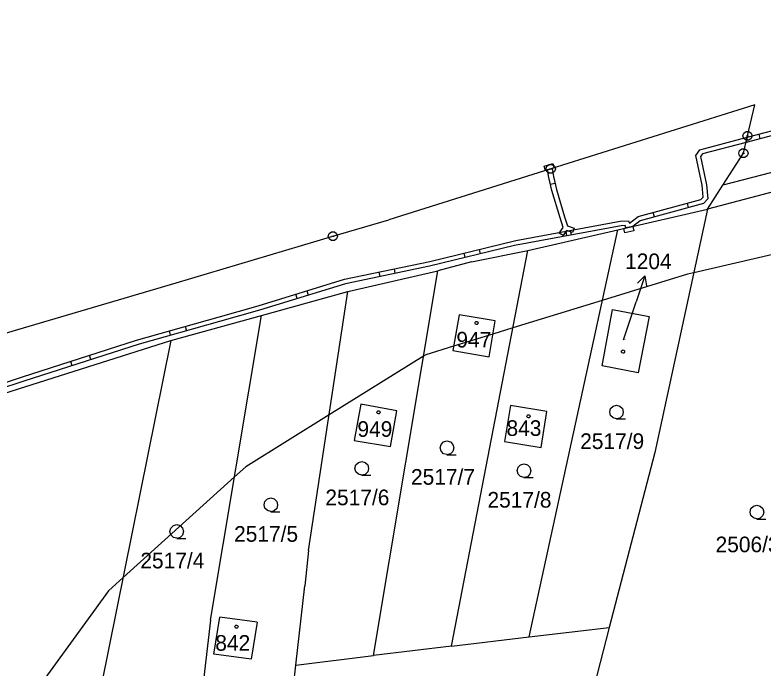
# Model space of a CAD drawing. Extents: x -760611 to -758411, y -1176479 to -1174807.
# Drawn here: x -759359.7 to -759278.5, y -1175126.3 to -1175055.4 of the extents above; entities that cross this region are included whole.
import ezdxf

# ---------------------------------------------------------------- set-up
doc = ezdxf.new("R2010")
doc.units = 0
for name, color, linetype in [('1', 7, 'Continuous'), ('11', 7, 'Continuous'), ('12', 7, 'Continuous'), ('13', 7, 'Continuous'), ('2', 7, 'Continuous'), ('3', 7, 'Continuous'), ('5', 7, 'Continuous'), ('7', 7, 'Continuous'), ('8', 7, 'Continuous')]:
    doc.layers.add(name, color=color, linetype=linetype)

msp = doc.modelspace()

# ---------------------------------------------------------------- linework, layer by layer
at = {"layer": '1'}
for p, q in [((-759279.37, -1175065.13), (-759301.53, -1175072.1)), ((-759280.16, -1175068.52), (-759279.37, -1175065.13)), ((-759258.67, -1175067.6), (-759282.82, -1175073.86)), ((-759280.6, -1175070.4), (-759280.16, -1175068.52)), ((-759261.9, -1175070.45), (-759284.49, -1175076.48)), ((-759282.82, -1175073.86), (-759280.6, -1175070.4)), ((-759301.53, -1175072.1), (-759319.13, -1175077.63)), ((-759284.49, -1175076.48), (-759282.82, -1175073.86)), ((-759294.26, -1175078.71), (-759284.49, -1175076.48)), ((-759284.49, -1175076.48), (-759290.24, -1175102.91)), ((-759325.19, -1175079.42), (-759319.13, -1175077.63)), ((-759342.24, -1175084.47), (-759325.19, -1175079.42)), ((-759304.03, -1175080.95), (-759294.26, -1175078.71)), ((-759303.86, -1175122.94), (-759294.26, -1175078.71)), ((-759312.31, -1175123.94), (-759304.03, -1175080.95)), ((-759310.13, -1175082.21), (-759304.03, -1175080.95)), ((-759310.13, -1175082.21), (-759313.8, -1175083.18)), ((-759323.57, -1175085.41), (-759313.8, -1175083.18)), ((-759320.78, -1175124.97), (-759313.8, -1175083.18)), ((-759367.91, -1175092.06), (-759342.24, -1175084.47)), ((-759332.94, -1175088.01), (-759323.57, -1175085.41)), ((-759327.86, -1175113.56), (-759323.57, -1175085.41)), ((-759295.95, -1175093.48), (-759294.82, -1175087.38)), ((-759294.82, -1175087.38), (-759290.84, -1175088.13)), ((-759342.79, -1175090.74), (-759332.94, -1175088.01)), ((-759338.48, -1175121.14), (-759332.94, -1175088.01)), ((-759311.49, -1175087.95), (-759312.16, -1175091.83)), ((-759307.58, -1175088.59), (-759311.49, -1175087.95)), ((-759290.84, -1175088.13), (-759292.04, -1175094.25)), ((-759308.22, -1175092.52), (-759307.58, -1175088.59)), ((-759367.67, -1175098.62), (-759342.79, -1175090.74)), ((-759342.79, -1175090.74), (-759352.98, -1175141.22)), ((-759312.16, -1175091.83), (-759308.22, -1175092.52)), ((-759292.04, -1175094.25), (-759295.95, -1175093.48)), ((-759322.17, -1175097.65), (-759322.9, -1175101.62)), ((-759318.26, -1175098.38), (-759322.17, -1175097.65)), ((-759305.9, -1175097.82), (-759306.54, -1175101.72)), ((-759301.95, -1175098.47), (-759305.9, -1175097.82)), ((-759318.94, -1175102.27), (-759318.26, -1175098.38)), ((-759302.59, -1175102.37), (-759301.95, -1175098.47)), ((-759322.9, -1175101.62), (-759318.94, -1175102.27)), ((-759306.54, -1175101.72), (-759302.59, -1175102.37)), ((-759290.24, -1175102.91), (-759295.17, -1175121.91)), ((-759327.86, -1175113.56), (-759328.24, -1175117.41)), ((-759329.21, -1175126), (-759328.24, -1175117.41)), ((-759338.12, -1175124.82), (-759337.47, -1175120.8)), ((-759333.44, -1175121.34), (-759337.47, -1175120.8)), ((-759338.48, -1175121.14), (-759340.03, -1175133.95)), ((-759333.44, -1175121.34), (-759334.07, -1175125.37)), ((-759303.86, -1175122.94), (-759295.17, -1175121.91)), ((-759295.17, -1175121.91), (-759298.25, -1175133.73)), ((-759312.31, -1175123.94), (-759303.86, -1175122.94)), ((-759312.31, -1175123.94), (-759320.78, -1175124.97)), ((-759334.07, -1175125.37), (-759338.12, -1175124.82)), ((-759329.21, -1175126), (-759320.78, -1175124.97)), ((-759330.67, -1175137.98), (-759329.21, -1175126))]:
    msp.add_line(p, q, dxfattribs=at)
at = {"layer": '11'}
msp.add_lwpolyline([(-759277.4, -1175081.41), (-759285.99, -1175083.38), (-759286.68, -1175083.54), (-759295.93, -1175086.38), (-759305.65, -1175089.38), (-759307.82, -1175090.04), (-759312.08, -1175091.35), (-759315.12, -1175092.29), (-759315.34, -1175092.43), (-759325.61, -1175098.82), (-759334.67, -1175104.46), (-759335.87, -1175105.55), (-759347.99, -1175116.51), (-759349.56, -1175117.93), (-759372.57, -1175149.55), (-759378.11, -1175156.29), (-759381.94, -1175161.35), (-759383.07, -1175162.46), (-759387.05, -1175166.4), (-759387.91, -1175169.78), (-759407.11, -1175194.59)], dxfattribs=at)
at = {"layer": '12'}
for p, q in [((-759295.95, -1175093.48), (-759294.82, -1175087.38)), ((-759294.82, -1175087.38), (-759290.84, -1175088.13)), ((-759311.49, -1175087.95), (-759312.16, -1175091.83)), ((-759307.58, -1175088.59), (-759311.49, -1175087.95)), ((-759290.84, -1175088.13), (-759292.04, -1175094.25)), ((-759308.22, -1175092.52), (-759307.58, -1175088.59)), ((-759312.16, -1175091.83), (-759308.22, -1175092.52)), ((-759292.04, -1175094.25), (-759295.95, -1175093.48)), ((-759322.17, -1175097.65), (-759322.9, -1175101.62)), ((-759318.26, -1175098.38), (-759322.17, -1175097.65)), ((-759305.9, -1175097.82), (-759306.54, -1175101.72)), ((-759301.95, -1175098.47), (-759305.9, -1175097.82)), ((-759318.94, -1175102.27), (-759318.26, -1175098.38)), ((-759302.59, -1175102.37), (-759301.95, -1175098.47)), ((-759322.9, -1175101.62), (-759318.94, -1175102.27)), ((-759306.54, -1175101.72), (-759302.59, -1175102.37)), ((-759338.12, -1175124.82), (-759337.47, -1175120.8)), ((-759333.44, -1175121.34), (-759337.47, -1175120.8)), ((-759333.44, -1175121.34), (-759334.07, -1175125.37)), ((-759334.07, -1175125.37), (-759338.12, -1175124.82))]:
    msp.add_line(p, q, dxfattribs=at)
at = {"layer": '13'}
for p, q in [((-759285.33, -1175070.01), (-759280.19, -1175068.65)), ((-759280.19, -1175068.65), (-759280.32, -1175069.22)), ((-759278.78, -1175068.818), (-759278.907, -1175068.335)), ((-759280.32, -1175069.22), (-759285.03, -1175070.45)), ((-759285.78, -1175070.64), (-759285.33, -1175070.01)), ((-759285.03, -1175070.45), (-759285.25, -1175070.75)), ((-759285.1, -1175073.88), (-759285.78, -1175070.64)), ((-759285.25, -1175070.75), (-759284.6, -1175073.82)), ((-759301.87, -1175072.2), (-759301.39, -1175072.05)), ((-759301.39, -1175072.05), (-759301.87, -1175072.2)), ((-759301.564, -1175073.756), (-759301.077, -1175073.64)), ((-759284.98, -1175075.17), (-759285.1, -1175073.88)), ((-759284.6, -1175073.82), (-759284.46, -1175075.35)), ((-759285.21, -1175075.42), (-759284.98, -1175075.17)), ((-759284.46, -1175075.35), (-759284.95, -1175075.86)), ((-759292.03, -1175077.27), (-759285.21, -1175075.42)), ((-759284.95, -1175075.86), (-759291.81, -1175077.73)), ((-759286.722, -1175075.83), (-759286.591, -1175076.313)), ((-759290.256, -1175077.306), (-759290.388, -1175076.824)), ((-759305.31, -1175079.88), (-759293.99, -1175077.77)), ((-759293.99, -1175077.77), (-759293.07, -1175077.74)), ((-759293.07, -1175077.74), (-759292.99, -1175077.98)), ((-759292.99, -1175077.98), (-759292.03, -1175077.27)), ((-759291.81, -1175077.73), (-759292.63, -1175078.34)), ((-759293.87, -1175078.27), (-759305.47, -1175080.42)), ((-759293.43, -1175078.26), (-759293.87, -1175078.27)), ((-759293.6, -1175078.56), (-759293.36, -1175078.5)), ((-759293.49, -1175079.05), (-759293.6, -1175078.56)), ((-759293.36, -1175078.5), (-759293.43, -1175078.26)), ((-759292.63, -1175078.34), (-759293.36, -1175078.5)), ((-759293.36, -1175078.5), (-759292.63, -1175078.34)), ((-759292.63, -1175078.34), (-759292.51, -1175078.82)), ((-759299.903, -1175078.872), (-759299.812, -1175079.364)), ((-759299.278, -1175079.272), (-759299.369, -1175078.781)), ((-759292.51, -1175078.82), (-759293.49, -1175079.05)), ((-759314.65, -1175082.15), (-759305.31, -1175079.88)), ((-759305.47, -1175080.42), (-759314.69, -1175082.67)), ((-759309.306, -1175080.851), (-759309.188, -1175081.337)), ((-759310.813, -1175081.724), (-759310.932, -1175081.238)), ((-759323.94, -1175084.08), (-759314.65, -1175082.15)), ((-759314.69, -1175082.67), (-759323.82, -1175084.57)), ((-759320.075, -1175083.791), (-759320.177, -1175083.301)), ((-759318.555, -1175082.961), (-759318.453, -1175083.451)), ((-759333.3, -1175086.97), (-759323.94, -1175084.08)), ((-759323.82, -1175084.57), (-759333.16, -1175087.45)), ((-759329.076, -1175086.191), (-759329.223, -1175085.713)), ((-759328.045, -1175085.347), (-759327.898, -1175085.825)), ((-759337.67, -1175088.2), (-759333.3, -1175086.97)), ((-759333.16, -1175087.45), (-759337.53, -1175088.68)), ((-759346.54, -1175090.7), (-759337.67, -1175088.2)), ((-759337.53, -1175088.68), (-759346.24, -1175091.14)), ((-759341.246, -1175089.208), (-759341.11, -1175089.689)), ((-759342.823, -1175090.175), (-759342.959, -1175089.694)), ((-759358.93, -1175094.68), (-759346.54, -1175090.7)), ((-759346.24, -1175091.14), (-759358.77, -1175095.16)), ((-759351.477, -1175092.82), (-759351.63, -1175092.344)), ((-759353.694, -1175092.998), (-759353.541, -1175093.474)), ((-759365.39, -1175096.83), (-759358.93, -1175094.68)), ((-759358.77, -1175095.16), (-759365.23, -1175097.31))]:
    msp.add_line(p, q, dxfattribs=at)
msp.add_lwpolyline([(-759280.32, -1175069.22), (-759280.19, -1175068.65), (-759275.46, -1175067.4), (-759267.57, -1175065.52), (-759257.68, -1175064.32), (-759246.5, -1175060.39), (-759241.38, -1175059.01), (-759235.85, -1175057.24), (-759231.22, -1175055.37), (-759230.63, -1175055.61), (-759230.35, -1175056.06), (-759230.48, -1175056.77), (-759230.97, -1175056.01), (-759231.23, -1175055.9), (-759235.83, -1175057.76), (-759241.1, -1175059.45), (-759246.41, -1175060.91), (-759257.6, -1175064.67), (-759257.79, -1175064.7), (-759260.43, -1175065.05), (-759266.85, -1175065.91), (-759275.26, -1175067.9)], close=True, dxfattribs=at)
for points in [[(-759301.87, -1175072.2), (-759302.12, -1175072.28), (-759302.26, -1175071.8), (-759301.31, -1175071.5)], [(-759301.31, -1175071.5), (-759301.16, -1175071.98), (-759301.39, -1175072.05)], [(-759301.39, -1175072.05), (-759301.24, -1175072.92), (-759300.92, -1175074.32), (-759300.03, -1175077.29), (-759299.72, -1175078.3), (-759299, -1175078.54)], [(-759299, -1175078.54), (-759299.16, -1175079.02), (-759299.82, -1175078.8), (-759300.18, -1175079.35), (-759300.6, -1175079.07), (-759300.19, -1175078.46), (-759300.51, -1175077.43), (-759301.4, -1175074.44), (-759301.74, -1175073.02), (-759301.87, -1175072.2)]]:
    msp.add_lwpolyline(points, dxfattribs=at)
at = {"layer": '3'}
for points in [[(-759294.38, -1175099.25), (-759294.76, -1175099.15), (-759295.03, -1175098.88), (-759295.13, -1175098.51), (-759295.03, -1175098.14), (-759294.76, -1175097.87), (-759294.39, -1175097.77), (-759294.02, -1175097.87), (-759293.75, -1175098.14), (-759293.65, -1175098.52), (-759293.75, -1175098.9), (-759294.02, -1175099.17), (-759294.4, -1175099.27), (-759293.4, -1175099.27)], [(-759312.8, -1175103.14), (-759313.18, -1175103.04), (-759313.45, -1175102.77), (-759313.55, -1175102.4), (-759313.45, -1175102.03), (-759313.18, -1175101.76), (-759312.81, -1175101.66), (-759312.44, -1175101.76), (-759312.17, -1175102.03), (-759312.07, -1175102.41), (-759312.17, -1175102.79), (-759312.44, -1175103.06), (-759312.82, -1175103.16), (-759311.82, -1175103.16)], [(-759322.05, -1175105.37), (-759322.43, -1175105.27), (-759322.7, -1175105), (-759322.8, -1175104.63), (-759322.7, -1175104.26), (-759322.43, -1175103.99), (-759322.06, -1175103.89), (-759321.69, -1175103.99), (-759321.42, -1175104.26), (-759321.32, -1175104.64), (-759321.42, -1175105.02), (-759321.69, -1175105.29), (-759322.07, -1175105.39), (-759321.07, -1175105.39)], [(-759304.42, -1175105.62), (-759304.8, -1175105.52), (-759305.07, -1175105.25), (-759305.17, -1175104.88), (-759305.07, -1175104.51), (-759304.8, -1175104.24), (-759304.43, -1175104.14), (-759304.06, -1175104.24), (-759303.79, -1175104.51), (-759303.69, -1175104.89), (-759303.79, -1175105.27), (-759304.06, -1175105.54), (-759304.44, -1175105.64), (-759303.44, -1175105.64)], [(-759331.93, -1175109.33), (-759332.31, -1175109.23), (-759332.58, -1175108.96), (-759332.68, -1175108.59), (-759332.58, -1175108.22), (-759332.31, -1175107.95), (-759331.94, -1175107.85), (-759331.57, -1175107.95), (-759331.3, -1175108.22), (-759331.2, -1175108.6), (-759331.3, -1175108.98), (-759331.57, -1175109.25), (-759331.95, -1175109.35), (-759330.95, -1175109.35)], [(-759279.13, -1175110.12), (-759279.51, -1175110.02), (-759279.78, -1175109.75), (-759279.88, -1175109.38), (-759279.78, -1175109.01), (-759279.51, -1175108.74), (-759279.14, -1175108.64), (-759278.77, -1175108.74), (-759278.5, -1175109.01), (-759278.4, -1175109.39), (-759278.5, -1175109.77), (-759278.77, -1175110.04), (-759279.15, -1175110.14), (-759278.15, -1175110.14)], [(-759342.15, -1175112.23), (-759342.53, -1175112.13), (-759342.8, -1175111.86), (-759342.9, -1175111.49), (-759342.8, -1175111.12), (-759342.53, -1175110.85), (-759342.16, -1175110.75), (-759341.79, -1175110.85), (-759341.52, -1175111.12), (-759341.42, -1175111.5), (-759341.52, -1175111.88), (-759341.79, -1175112.15), (-759342.17, -1175112.25), (-759341.17, -1175112.25)]]:
    msp.add_lwpolyline(points, dxfattribs=at)
at = {"layer": '5'}
for points in [[(-759309.6, -1175088.66), (-759309.5, -1175088.68), (-759309.45, -1175088.77), (-759309.43, -1175088.83), (-759309.45, -1175088.92), (-759309.53, -1175088.99), (-759309.6, -1175089), (-759309.69, -1175088.97), (-759309.75, -1175088.91), (-759309.77, -1175088.83), (-759309.75, -1175088.74), (-759309.67, -1175088.67)], [(-759293.68, -1175091.77), (-759293.58, -1175091.79), (-759293.53, -1175091.88), (-759293.51, -1175091.94), (-759293.53, -1175092.03), (-759293.61, -1175092.1), (-759293.68, -1175092.11), (-759293.77, -1175092.08), (-759293.83, -1175092.02), (-759293.85, -1175091.94), (-759293.83, -1175091.85), (-759293.75, -1175091.78)], [(-759320.25, -1175098.37), (-759320.15, -1175098.39), (-759320.1, -1175098.48), (-759320.08, -1175098.54), (-759320.1, -1175098.63), (-759320.18, -1175098.7), (-759320.25, -1175098.71), (-759320.34, -1175098.68), (-759320.4, -1175098.62), (-759320.42, -1175098.54), (-759320.4, -1175098.45), (-759320.32, -1175098.38)], [(-759303.95, -1175098.81), (-759303.85, -1175098.83), (-759303.8, -1175098.92), (-759303.78, -1175098.98), (-759303.8, -1175099.07), (-759303.88, -1175099.14), (-759303.95, -1175099.15), (-759304.04, -1175099.12), (-759304.1, -1175099.06), (-759304.12, -1175098.98), (-759304.1, -1175098.89), (-759304.02, -1175098.82)], [(-759335.67, -1175121.67), (-759335.57, -1175121.69), (-759335.52, -1175121.78), (-759335.5, -1175121.84), (-759335.52, -1175121.93), (-759335.6, -1175122), (-759335.67, -1175122.01), (-759335.76, -1175121.98), (-759335.82, -1175121.92), (-759335.84, -1175121.84), (-759335.82, -1175121.75), (-759335.74, -1175121.68)]]:
    msp.add_lwpolyline(points, close=True, dxfattribs=at)
at = {"layer": '7'}
for p in [(-759291.3, -1175083.704), (-759293.62, -1175090.67)]:
    msp.add_line(p, (-759292.25, -1175086.55), dxfattribs=at)
msp.add_lwpolyline([(-759292.091, -1175084.495), (-759291.3, -1175083.704), (-759291.142, -1175084.811)], dxfattribs=at)
at = {"layer": '8'}
for p, q in [((-759280.28, -1175068.52), (-759280.04, -1175068.52)), ((-759280.72, -1175070.4), (-759280.48, -1175070.4)), ((-759301.65, -1175072.1), (-759301.41, -1175072.1)), ((-759325.31, -1175079.42), (-759325.07, -1175079.42))]:
    msp.add_line(p, q, dxfattribs=at)
for points in [[(-759280.01, -1175068.04), (-759279.76, -1175068.22), (-759279.66, -1175068.51), (-759279.76, -1175068.8), (-759280.01, -1175068.98), (-759280.32, -1175068.98), (-759280.57, -1175068.8), (-759280.67, -1175068.51), (-759280.57, -1175068.22), (-759280.32, -1175068.04)], [(-759280.45, -1175069.92), (-759280.2, -1175070.1), (-759280.1, -1175070.39), (-759280.2, -1175070.68), (-759280.45, -1175070.86), (-759280.76, -1175070.86), (-759281.01, -1175070.68), (-759281.11, -1175070.39), (-759281.01, -1175070.1), (-759280.76, -1175069.92)], [(-759301.38, -1175071.62), (-759301.13, -1175071.8), (-759301.03, -1175072.09), (-759301.13, -1175072.38), (-759301.38, -1175072.56), (-759301.69, -1175072.56), (-759301.94, -1175072.38), (-759302.04, -1175072.09), (-759301.94, -1175071.8), (-759301.69, -1175071.62)], [(-759325.04, -1175078.94), (-759324.79, -1175079.12), (-759324.69, -1175079.41), (-759324.79, -1175079.7), (-759325.04, -1175079.88), (-759325.35, -1175079.88), (-759325.6, -1175079.7), (-759325.7, -1175079.41), (-759325.6, -1175079.12), (-759325.35, -1175078.94)]]:
    msp.add_lwpolyline(points, close=True, dxfattribs=at)

# ---------------------------------------------------------------- texts
at = {"layer": '2'}
for s, height, p in [('947', 1.7, (-759311.784, -1175091.5)), ('1204', 0.1, (-759293.597, -1175090.67)), ('949', 1.7, (-759322.534, -1175101.21)), ('843', 1.7, (-759306.338, -1175101.11)), ('2517/9', 1.7, (-759298.335, -1175102.53)), ('2517/7', 1.7, (-759316.715, -1175106.41)), ('2517/6', 1.7, (-759326.015, -1175108.64)), ('2517/8', 1.7, (-759308.405, -1175108.9)), ('2517/5', 1.7, (-759335.932, -1175112.61)), ('2506/3', 1.7, (-759283.627, -1175113.75)), ('2517/4', 1.7, (-759346.115, -1175115.5)), ('842', 1.7, (-759337.975, -1175124.45))]:
    msp.add_text(s, height=height, dxfattribs=at).set_placement(p)
at = {"layer": '7'}
msp.add_text('1204', height=1.7, dxfattribs=at).set_placement((-759293.456, -1175082.99))

doc.saveas('drawing.dxf')
